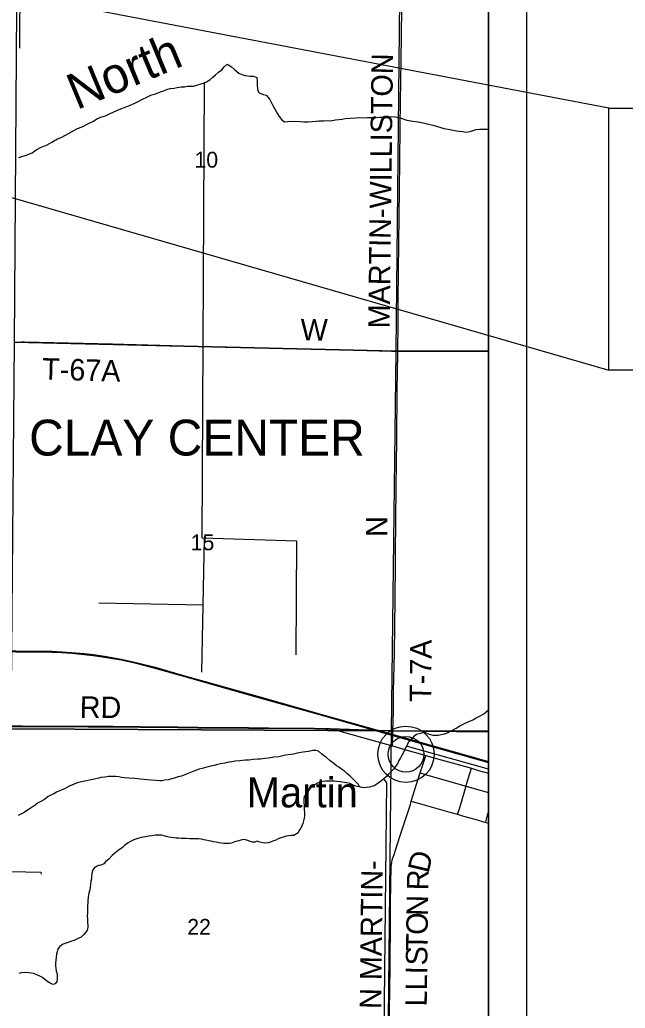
# Model space of a CAD drawing. Extents: x 0 to 34, y 0 to 22.
# Drawn here: x 7.662 to 9.261, y 16.658 to 19.268 of the extents above; entities that cross this region are included whole.
import ezdxf

# ---------------------------------------------------------------- set-up
doc = ezdxf.new("R2010")
doc.units = 0
for name, color, linetype in [('Default', 7, 'Continuous'), ('GM_X_Corporation_Text', 7, 'Continuous'), ('GM_X_County_Road', 7, 'Continuous'), ('GM_X_County_Road_Text', 7, 'Continuous'), ('GM_X_Interstate_Route', 7, 'Continuous'), ('GM_X_Major_River', 7, 'Continuous'), ('GM_X_Minor_River', 7, 'Continuous'), ('GM_X_Minor_River_Text', 7, 'Continuous'), ('GM_X_Rail_Line', 7, 'Continuous'), ('GM_X_Section', 7, 'Continuous'), ('GM_X_Section_Text', 7, 'Continuous'), ('GM_X_Township_Road', 7, 'Continuous'), ('GM_X_Township_Road_Text', 7, 'Continuous'), ('GM_X_Unincorporated', 7, 'Continuous'), ('GM_X_Unincorporated_Location', 7, 'Continuous'), ('GM_X_Unincorporated_Text', 7, 'Continuous'), ('SH_Data', 7, 'Continuous'), ('SH_Text', 7, 'Continuous')]:
    doc.layers.add(name, color=color, linetype=linetype)

msp = doc.modelspace()

# ---------------------------------------------------------------- linework, layer by layer
at = {"layer": 'Default'}
for points in [[(8.9, 18.3933), (8.9, 19.4085), (8.666, 19.4088), (8.6554, 18.3927)], [(8.9, 17.3884), (8.9, 18.3933), (8.6554, 18.3927), (8.6426, 17.3907)], [(8.9, 16.3752), (8.9, 17.3884), (8.6426, 17.3907), (8.6324, 16.375)]]:
    msp.add_lwpolyline(points, close=True, dxfattribs=at)
at = {"layer": 'GM_X_County_Road'}
for points in [[(7.6615, 19.1928), (7.6618, 19.2257), (7.663, 19.3406), (7.6641, 19.424)], [(7.6402, 17.4023), (7.6683, 17.4021), (7.7243, 17.4019), (7.8426, 17.4016), (7.908, 17.4013), (7.9796, 17.4005), (8.0792, 17.3999), (8.1321, 17.399), (8.266, 17.3978), (8.3189, 17.3974), (8.4403, 17.3965), (8.4714, 17.3958), (8.4806, 17.3953), (8.4898, 17.3941), (8.4989, 17.3923), (8.511, 17.3893), (8.5888, 17.3671), (8.6307, 17.3552), (8.6461, 17.3509)], [(8.6461, 17.3509), (8.6846, 17.3398), (8.6875, 17.339)], [(8.6875, 17.339), (8.7191, 17.33), (8.7346, 17.3256)], [(8.7198, 17.2796), (8.7303, 17.3119), (8.7346, 17.3256)], [(8.7346, 17.3256), (8.7747, 17.3142), (8.8136, 17.3034), (8.855, 17.2917)], [(8.696, 17.2047), (8.7048, 17.2329), (8.7198, 17.2796)], [(8.855, 17.2917), (8.8737, 17.2864), (8.9, 17.279)], [(8.6342, 16.3763), (8.6349, 16.395), (8.6355, 16.4353), (8.6362, 16.4974), (8.6371, 16.5811), (8.6381, 16.6525), (8.6401, 16.7673), (8.6405, 16.8107), (8.641, 16.851), (8.641, 16.879), (8.6415, 16.9251), (8.6423, 16.9966), (8.6427, 17.0214), (8.6428, 17.0275), (8.6432, 17.0337), (8.6436, 17.0377), (8.6447, 17.0437), (8.6458, 17.0492), (8.6475, 17.055), (8.6495, 17.0616), (8.666, 17.1117), (8.684, 17.1672), (8.6935, 17.1966), (8.696, 17.2047)]]:
    msp.add_lwpolyline(points, dxfattribs=at)
at = {"layer": 'GM_X_Interstate_Route'}
for points in [[(7.6399, 17.4028), (7.6681, 17.4026), (7.7241, 17.4025), (7.8424, 17.4022), (7.9078, 17.4018), (7.9794, 17.4011), (8.079, 17.4004), (8.1319, 17.3996), (8.2657, 17.3984), (8.3187, 17.398), (8.44, 17.397), (8.4711, 17.3964), (8.4804, 17.3959), (8.6346, 17.3907), (8.6467, 17.3907), (8.6473, 17.3907), (8.9, 17.3895), (8.9, 20.9)], [(8.9, 14.1), (8.9, 17.3895), (8.6473, 17.3907), (8.6467, 17.3907), (8.6346, 17.3907), (8.4804, 17.3959), (8.4711, 17.3964), (8.44, 17.397), (8.3187, 17.398), (8.2657, 17.3984), (8.1319, 17.3996), (8.079, 17.4004), (7.9794, 17.4011), (7.9078, 17.4018), (7.8424, 17.4022), (7.7241, 17.4025), (7.6681, 17.4026), (7.6399, 17.4028)]]:
    msp.add_lwpolyline(points, dxfattribs=at)
at = {"layer": 'GM_X_Major_River'}
for points in [[(8.7329, 17.3867), (8.7408, 17.3829), (8.7469, 17.381), (8.753, 17.3794), (8.7609, 17.379), (8.7674, 17.3794), (8.7749, 17.3809), (8.7837, 17.3832), (8.7931, 17.3859), (8.8034, 17.3915), (8.8144, 17.3976), (8.8246, 17.4037), (8.8329, 17.4082), (8.8436, 17.4136), (8.8508, 17.4162), (8.8583, 17.42), (8.8674, 17.4246), (8.8811, 17.4318), (8.8875, 17.4359), (8.8932, 17.4401), (8.9, 17.4459)], [(8.7329, 17.3867), (8.7268, 17.3851), (8.7207, 17.384), (8.7097, 17.381), (8.7033, 17.3764), (8.6972, 17.37), (8.6915, 17.3647), (8.687, 17.3582), (8.6847, 17.3525), (8.6809, 17.3457), (8.6764, 17.3354), (8.6711, 17.3259), (8.6676, 17.3198), (8.662, 17.3104), (8.6593, 17.3039), (8.6532, 17.2955), (8.6494, 17.2899), (8.6422, 17.2826), (8.6369, 17.2769), (8.6301, 17.2701), (8.618, 17.2595), (8.6051, 17.2496), (8.5983, 17.2458), (8.5922, 17.2439), (8.5854, 17.242), (8.5778, 17.2409), (8.5713, 17.2401), (8.5661, 17.2411)], [(8.5661, 17.2411), (8.5588, 17.2432), (8.5562, 17.2493), (8.5479, 17.258), (8.541, 17.2648), (8.5338, 17.2717), (8.5259, 17.2782), (8.5194, 17.2839), (8.5115, 17.2892), (8.5043, 17.2945), (8.4982, 17.2987), (8.4914, 17.3044), (8.4815, 17.3116), (8.4717, 17.32), (8.4645, 17.3257), (8.4584, 17.3302), (8.4512, 17.3371), (8.444, 17.339), (8.4357, 17.339), (8.4247, 17.3363), (8.4103, 17.3341), (8.3985, 17.3322), (8.3845, 17.3295), (8.364, 17.3261), (8.3462, 17.3223), (8.3329, 17.3208), (8.3189, 17.3186), (8.3087, 17.3174), (8.303, 17.3167), (8.2973, 17.3163), (8.2897, 17.3155), (8.278, 17.3148), (8.2666, 17.3136), (8.2579, 17.3129), (8.2503, 17.3121), (8.2427, 17.3118), (8.2306, 17.3102), (8.2219, 17.3091), (8.2097, 17.3072), (8.2037, 17.3057), (8.1923, 17.3034), (8.1843, 17.3015), (8.1741, 17.2989), (8.1627, 17.2962), (8.1555, 17.2947), (8.1438, 17.2913), (8.1354, 17.2898), (8.1282, 17.2868), (8.1214, 17.2841), (8.1127, 17.2807), (8.1043, 17.2773), (8.0975, 17.2743), (8.0888, 17.2712), (8.0805, 17.2689), (8.0721, 17.2663), (8.063, 17.264), (8.0536, 17.2617), (8.0448, 17.2602), (8.038, 17.2587), (8.0304, 17.2583), (8.0221, 17.2599), (8.0081, 17.2606), (7.9978, 17.2614), (7.9899, 17.2622), (7.9793, 17.2633), (7.9656, 17.2648), (7.9501, 17.2656), (7.9379, 17.2668), (7.9304, 17.2679), (7.9232, 17.269), (7.9148, 17.2698), (7.9091, 17.2702), (7.9023, 17.2702), (7.8959, 17.2702), (7.8864, 17.2687), (7.8762, 17.2672), (7.8701, 17.266), (7.8625, 17.2638), (7.8504, 17.2615), (7.842, 17.2596), (7.8322, 17.2577), (7.825, 17.2562), (7.8136, 17.2532), (7.8034, 17.249), (7.792, 17.2448), (7.7795, 17.2372), (7.767, 17.2319), (7.7583, 17.2285), (7.7514, 17.2247), (7.7457, 17.2213), (7.7366, 17.2171), (7.7272, 17.2092), (7.7154, 17.2031), (7.7086, 17.1993), (7.7021, 17.194), (7.6915, 17.1871), (7.6821, 17.1815), (7.673, 17.1754), (7.6642, 17.1705), (7.657, 17.167)]]:
    msp.add_lwpolyline(points, dxfattribs=at)
at = {"layer": 'GM_X_Minor_River'}
msp.add_line((8.9, 17.2894), (8.6862, 17.3491), dxfattribs=at)
for points in [[(8.1495, 19.102), (8.1548, 19.1039), (8.1639, 19.1092), (8.1715, 19.1164), (8.1791, 19.1231), (8.1871, 19.1299), (8.1951, 19.1363), (8.2012, 19.1435), (8.2096, 19.1507), (8.2213, 19.1442), (8.2288, 19.1366), (8.2402, 19.1274), (8.2481, 19.1232), (8.2572, 19.1205), (8.2704, 19.1193), (8.2791, 19.1189), (8.2875, 19.1154), (8.2889, 19.1055), (8.2889, 19.0979), (8.2896, 19.0828), (8.2945, 19.0755), (8.3043, 19.0709), (8.3126, 19.0686), (8.3224, 19.0575), (8.3265, 19.0488), (8.3314, 19.0404), (8.3427, 19.0195), (8.3472, 19.0123), (8.3532, 19.0046), (8.3612, 18.9985), (8.3702, 18.9992), (8.3797, 19), (8.4036, 18.9998), (8.4123, 18.9987), (8.4237, 18.9986), (8.4445, 19.0004), (8.4517, 19.0015), (8.465, 19.0014), (8.4866, 19.0025), (8.4957, 19.0039), (8.5131, 19.0054), (8.5215, 19.0072), (8.5347, 19.0087), (8.5499, 19.0094), (8.5597, 19.0097), (8.5707, 19.0092), (8.5802, 19.0096), (8.5904, 19.0099), (8.5991, 19.0099), (8.6117, 19.0109), (8.6192, 19.0113), (8.6276, 19.0116), (8.6352, 19.012), (8.6439, 19.0123), (8.6545, 19.0122), (8.667, 19.0091), (8.6844, 19.0034), (8.7003, 19.0003), (8.7135, 18.999), (8.7275, 18.9963), (8.7525, 18.9894), (8.765, 18.9863), (8.7741, 18.9839), (8.7824, 18.9812), (8.7983, 18.9785), (8.807, 18.9766), (8.8153, 18.975), (8.8233, 18.9738), (8.8324, 18.9727), (8.8399, 18.9715), (8.8517, 18.9733), (8.8672, 18.9782), (8.8763, 18.9793), (8.9, 18.9791)], [(7.659, 18.9042), (7.67, 18.9079), (7.6795, 18.9105), (7.6871, 18.9139), (7.6943, 18.9165), (7.7049, 18.9244), (7.7167, 18.9312), (7.7338, 18.9375), (7.7467, 18.9451), (7.7615, 18.9541), (7.7729, 18.9582), (7.79, 18.9676), (7.7984, 18.9721), (7.806, 18.977), (7.814, 18.9808), (7.8261, 18.9857), (7.8417, 18.9932), (7.8561, 19.0007), (7.8648, 19.0063), (7.8759, 19.0108), (7.8884, 19.0146), (7.9002, 19.0206), (7.91, 19.0247), (7.9199, 19.0292), (7.9309, 19.0341), (7.9442, 19.0389), (7.9579, 19.0446), (7.9658, 19.0476), (7.9761, 19.0532), (7.9863, 19.0581), (7.997, 19.0637), (8.0076, 19.069), (8.0198, 19.0727), (8.0338, 19.0776), (8.0414, 19.0802), (8.0505, 19.0836), (8.0592, 19.0866), (8.0691, 19.0876), (8.0774, 19.0891), (8.0877, 19.0906), (8.0964, 19.0913), (8.1043, 19.0924), (8.1119, 19.0927), (8.121, 19.0931), (8.1495, 19.102)], [(8.3917, 17.5916), (8.3937, 17.8917), (8.1439, 17.8995), (8.1495, 19.1029)], [(8.1484, 17.8993), (8.1419, 17.5454)], [(8.1452, 17.7224), (7.8705, 17.728)], [(8.5661, 17.2411), (8.5653, 17.2413), (8.5592, 17.2424), (8.5528, 17.2436), (8.5471, 17.2455), (8.541, 17.2485), (8.5334, 17.2512), (8.5255, 17.2538), (8.5137, 17.2554), (8.5077, 17.2561), (8.4997, 17.2573), (8.494, 17.258), (8.4751, 17.2581), (8.469, 17.2577), (8.4626, 17.2573), (8.4557, 17.255), (8.4478, 17.2528), (8.4406, 17.2482), (8.4349, 17.2444), (8.4284, 17.2376), (8.4231, 17.2307), (8.4182, 17.2235), (8.4129, 17.2175), (8.4125, 17.211), (8.4125, 17.2011), (8.4129, 17.1939), (8.4133, 17.1836), (8.414, 17.1745), (8.414, 17.1673), (8.4129, 17.1605), (8.4114, 17.1529), (8.4091, 17.146), (8.4064, 17.1396), (8.4042, 17.1339), (8.4, 17.1282), (8.3973, 17.1217), (8.386, 17.1145), (8.3788, 17.1142), (8.3719, 17.1134), (8.3655, 17.1126), (8.3579, 17.11), (8.3511, 17.1081), (8.3439, 17.1054), (8.3378, 17.1024), (8.3321, 17.1005), (8.3238, 17.0971), (8.3177, 17.0952), (8.3094, 17.0944), (8.3037, 17.0948), (8.2957, 17.0971), (8.2889, 17.0994), (8.2825, 17.0964), (8.2768, 17.0964), (8.2703, 17.0983), (8.2643, 17.1013), (8.2548, 17.104), (8.248, 17.1028), (8.2404, 17.1002), (8.229, 17.0975), (8.2214, 17.0945), (8.2154, 17.093), (8.2063, 17.0934), (8.2006, 17.0934), (8.1942, 17.0938), (8.1877, 17.0949), (8.1805, 17.0964), (8.1737, 17.0976), (8.1676, 17.0995), (8.1608, 17.1002), (8.1536, 17.1018), (8.1479, 17.1029), (8.1418, 17.1044), (8.135, 17.1052), (8.1229, 17.1052), (8.1108, 17.1056)], [(8.6229, 17.264), (8.6309, 17.2534), (8.611, 15.4343)], [(8.1108, 17.1056), (8.1013, 17.106), (8.0884, 17.1064), (8.0808, 17.1071), (8.0748, 17.1075), (8.0687, 17.1083), (8.0622, 17.1094), (8.0558, 17.1102), (8.0486, 17.1117), (8.0429, 17.1136), (8.0365, 17.1148), (8.0202, 17.1148), (8.0107, 17.1136), (8.0027, 17.1125), (7.9948, 17.111), (7.9879, 17.1098), (7.9823, 17.1091), (7.9766, 17.1076), (7.9686, 17.1049), (7.9629, 17.1026), (7.9542, 17.0985), (7.9481, 17.0954), (7.939, 17.0886), (7.933, 17.0825), (7.9216, 17.0749), (7.9129, 17.0677), (7.9053, 17.0613), (7.8973, 17.0522), (7.889, 17.0453), (7.8833, 17.0393), (7.8757, 17.0362), (7.87, 17.0347), (7.864, 17.0321), (7.8579, 17.0283), (7.8541, 17.0218), (7.8522, 17.0142), (7.8511, 17.0055), (7.8507, 16.9998), (7.8496, 16.9941), (7.8484, 16.9854), (7.8469, 16.9713), (7.8442, 16.9618), (7.8427, 16.9516), (7.8416, 16.9421), (7.8412, 16.9364), (7.8408, 16.9288), (7.8408, 16.9227), (7.8404, 16.917), (7.8404, 16.9109), (7.8401, 16.9018), (7.8404, 16.8953), (7.8404, 16.8896), (7.8408, 16.8836), (7.8416, 16.8779), (7.8416, 16.8714), (7.8397, 16.8646), (7.8351, 16.8581), (7.8298, 16.8524), (7.8241, 16.846), (7.8181, 16.8429), (7.8109, 16.8395), (7.8048, 16.8372), (7.7957, 16.8342), (7.7896, 16.8319), (7.7805, 16.8289), (7.7745, 16.8263), (7.7673, 16.8213), (7.762, 16.8149), (7.7601, 16.8073), (7.7589, 16.8012), (7.7582, 16.7932), (7.757, 16.7852), (7.7563, 16.7773), (7.7559, 16.7701), (7.7566, 16.764), (7.7582, 16.756), (7.7604, 16.7492), (7.7608, 16.7416), (7.7608, 16.7355), (7.7593, 16.729), (7.7547, 16.7226), (7.7487, 16.7211), (7.7418, 16.7245), (7.7335, 16.7298), (7.7278, 16.734), (7.7221, 16.7393), (7.7142, 16.7427), (7.707, 16.7469), (7.6983, 16.75), (7.6926, 16.7511), (7.6854, 16.7519), (7.6748, 16.7523), (7.6649, 16.7515), (7.6588, 16.7504)]]:
    msp.add_lwpolyline(points, dxfattribs=at)
at = {"layer": 'GM_X_Rail_Line'}
for points in [[(4.7039, 17.6237), (5.1874, 17.6209), (5.6534, 17.6172), (5.9221, 17.6153), (6.6307, 17.6096), (7.1327, 17.6059), (7.4891, 17.603), (7.6513, 17.6017), (7.7461, 17.6007), (7.7732, 17.5996), (7.7996, 17.5979), (7.8317, 17.5948), (7.856, 17.5922), (7.8859, 17.5877), (7.9297, 17.5801), (7.9694, 17.5712), (8.019, 17.5585), (8.0883, 17.5388), (8.2893, 17.4822), (8.4661, 17.4324), (8.6481, 17.3808), (8.9, 17.3095)], [(4.7039, 17.6214), (5.1874, 17.6186), (5.6534, 17.6149), (5.9221, 17.613), (6.6307, 17.6073), (7.1327, 17.6036), (7.489, 17.6007), (7.6513, 17.5994), (7.7461, 17.5984), (7.7731, 17.5973), (7.7994, 17.5956), (7.8314, 17.5925), (7.8557, 17.5899), (7.8855, 17.5854), (7.9292, 17.5778), (7.9689, 17.569), (8.0184, 17.5563), (8.0876, 17.5366), (8.2886, 17.48), (8.4655, 17.4302), (8.6474, 17.3785), (8.9, 17.3071)]]:
    msp.add_lwpolyline(points, dxfattribs=at)
at = {"layer": 'GM_X_Section'}
for points in [[(8.666, 19.4088), (8.6554, 18.3927), (7.6481, 18.4165), (7.6545, 19.4258)], [(8.6554, 18.3927), (8.6426, 17.3907), (7.639, 17.3962), (7.6481, 18.4165)], [(7.639, 17.3962), (8.6426, 17.3907), (8.6324, 16.375), (7.6303, 16.3805)]]:
    msp.add_lwpolyline(points, close=True, dxfattribs=at)
at = {"layer": 'GM_X_Township_Road'}
msp.add_line((8.8929, 17.1489), (8.9, 17.1469), dxfattribs=at)
for points in [[(8.6602, 18.3934), (8.6612, 18.4674), (8.6614, 18.5078), (8.6617, 18.5264), (8.6623, 18.6041), (8.6659, 18.8932), (8.667, 18.9864), (8.6678, 19.0517), (8.6695, 19.1604), (8.671, 19.2972), (8.6712, 19.3936), (8.6714, 19.4059)], [(7.6532, 18.4161), (7.6573, 18.4167), (7.6604, 18.4171), (7.6631, 18.4173), (7.6662, 18.4175), (7.6695, 18.4176), (7.6739, 18.4176), (7.907, 18.4122), (8.0624, 18.4077), (8.1121, 18.4062), (8.2054, 18.4038), (8.2831, 18.4021), (8.3298, 18.4009), (8.4479, 18.3983), (8.5785, 18.3952), (8.6438, 18.3935), (8.6602, 18.3934)], [(8.6476, 17.3901), (8.6486, 17.4417), (8.6494, 17.4946), (8.6514, 17.5972), (8.6531, 17.7369), (8.654, 17.8333), (8.6543, 17.8581), (8.656, 18.0353), (8.6577, 18.1597), (8.6589, 18.2902), (8.6601, 18.3866), (8.6602, 18.3934)], [(8.6602, 18.3934), (8.6718, 18.3933), (8.8148, 18.3938), (8.9, 18.3936)], [(8.6461, 17.3509), (8.6475, 17.3889), (8.6476, 17.3901)], [(8.7198, 17.2796), (8.7221, 17.2788), (8.7358, 17.2743), (8.7695, 17.2644), (8.8406, 17.2443)], [(8.8406, 17.2443), (8.8431, 17.2522), (8.8542, 17.2894), (8.855, 17.2917)], [(8.8179, 17.1703), (8.819, 17.1732), (8.8232, 17.1851), (8.8309, 17.2117), (8.8398, 17.2417), (8.8406, 17.2443)], [(8.8406, 17.2443), (8.862, 17.2383), (8.9, 17.2277)], [(8.696, 17.2047), (8.6986, 17.204), (8.7175, 17.1991), (8.7982, 17.1759), (8.8179, 17.1703)], [(8.8929, 17.1489), (8.8933, 17.1506), (8.8985, 17.1712), (8.9, 17.1762)], [(8.8179, 17.1703), (8.8342, 17.1658), (8.8639, 17.1571), (8.8929, 17.1489)], [(7.6362, 17.0194), (7.6376, 17.0193), (7.7175, 17.0174), (7.7178, 17.0121)]]:
    msp.add_lwpolyline(points, dxfattribs=at)
at = {"layer": 'GM_X_Unincorporated'}
for radius in [0.0744, 0.0472]:
    msp.add_circle((8.682, 17.3288), radius, dxfattribs=at)
at = {"layer": 'GM_X_Unincorporated_Location'}
msp.add_line((8.682, 17.3288), (8.682, 17.3288), dxfattribs=at)
at = {"layer": 'SH_Data'}
for p, q in [((9, 21), (9, 14)), ((8.9, 20.9), (8.9, 14.1))]:
    msp.add_line(p, q, dxfattribs=at)
at = {"layer": 'SH_Text'}
for points in [[(9.2181, 19.0346), (2.1904, 20.3744), (9.2181, 18.3428)], [(9.2181, 19.0346), (10.8094, 19.0346), (10.8094, 18.3428), (9.2181, 18.3428)]]:
    msp.add_lwpolyline(points, close=True, dxfattribs=at)

# ---------------------------------------------------------------- texts
at = {"layer": 'GM_X_Corporation_Text'}
msp.add_text('CLAY CENTER', height=0.094697, rotation=0, dxfattribs=at).set_placement((7.6864, 18.1175))
at = {"layer": 'GM_X_County_Road_Text'}
for s, height, rotation, p in [('RD', 0.05682, 359.5131, (7.8199, 17.425)), ('D', 0.0568, 76.5062, (8.7413, 17.0127)), ('N MARTIN-', 0.05682, 89.3516, (8.6164, 16.6562)), ('R', 0.0568, 89.0047, (8.7409, 16.9693)), ('N', 0.0568, 89.2532, (8.74, 16.9018)), ('O', 0.0568, 89.2736, (8.7393, 16.8518)), ('T', 0.0568, 89.2714, (8.7388, 16.8094)), ('S', 0.0568, 89.273, (8.7383, 16.771)), ('I', 0.0568, 89.274, (8.738, 16.7477)), ('L', 0.0568, 89.2781, (8.7375, 16.7052)), ('L', 0.0568, 89.2714, (8.7369, 16.6627))]:
    msp.add_text(s, height=height, rotation=rotation, dxfattribs=at).set_placement(p)
at = {"layer": 'GM_X_Minor_River_Text'}
msp.add_text('North', height=0.09476, rotation=22.5707, dxfattribs=at).set_placement((7.812, 19.0293))
at = {"layer": 'GM_X_Section_Text'}
for s, p in [('10', (8.1233, 18.8777)), ('15', (8.1133, 17.8674)), ('22', (8.1042, 16.8522))]:
    msp.add_text(s, height=0.04186, rotation=0, dxfattribs=at).set_placement(p)
at = {"layer": 'GM_X_Township_Road_Text'}
for s, height, rotation, p in [('MARTIN-WILLISTON', 0.056818, 89.2922, (8.6389, 18.4529)), ('W', 0.0568, 359.2752, (8.4032, 18.4217)), ('T-67A', 0.05682, 358.4457, (7.7202, 18.3182)), ('N', 0.0568, 90, (8.6331, 17.9027)), ('T-7A', 0.05682, 89.3637, (8.7483, 17.4667))]:
    msp.add_text(s, height=height, rotation=rotation, dxfattribs=at).set_placement(p)
at = {"layer": 'GM_X_Unincorporated_Text'}
msp.add_text('Martin', height=0.07898, rotation=0, dxfattribs=at).set_placement((8.2613, 17.1885))

doc.saveas('drawing.dxf')
